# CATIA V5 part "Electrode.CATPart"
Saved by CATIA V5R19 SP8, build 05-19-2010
Part number: Electrode
Nomenclature: 66
Material "Chrome": density 7190 kg/m3, Young's modulus 7e+10 Pa, Poisson ratio 0.3, thermal expansion 6.2e-06 1/K
Bounding box of the stored display mesh (mm): x -21 to 21, y -15 to 15, z 4.388 to 19.89
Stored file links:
  C:\Users\rphgr\Desktop\0_Tapis_TC520B_vitesse\Electrode.CATPart
  D:\Documents\1_Travail\1 - ac-limoges.fr\ac-limoges.fr\Emmanuel Maynard - STI2D_Turgot\3 - Supports\Tapis de course TC520B\Tapis de course TC520B_Ca\0_Tapis_TC520B_Conception.CATProduct
  D:\Documents\1_Travail\1 - ac-limoges.fr\ac-limoges.fr\Emmanuel Maynard - STI2D_Turgot\3 - Supports\Tapis de course TC520B\Tapis de course TC520B_Ca\Support Electrode_Sup.CATPart
  D:\Programmes\DassaultSysteme\win_b64\startup\materials\French\Catalog.CATMaterial
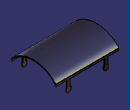
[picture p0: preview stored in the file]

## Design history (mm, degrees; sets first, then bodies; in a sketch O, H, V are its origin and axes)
AxisSystem1: origin (0, 0, 0), X (1, 0, 0), Y (0, 1, 0), Z (0, 0, 1)
Set1
  DatumSurface1
  DatumSurface2
Body1 (main body), material "Chrome"
  Sketch1 on YZ plane of AxisSystem1, origin (0, 0, 0), H (0, 1, 0), V (0, 0, 1)
    projected arc E1 centre (0, 0) radius 19.4 from (14.5, 12.8884) to (-14.5, 12.8884) ccw from face of DatumSurface1
    line L1 (14.5, 12.8884) -> (14.5, 2.8884)
    line L2 (-14.5, 12.8884) -> (-14.5, 2.8884)
    length L1 = 10
    length L2 = 10
    vertical: L1 V, L2 V
  Pad1: profile Sketch1, direction (-1, 0, 0), length 21, mirrored extent, thin wall 0, second thickness 0.5
  Sketch2 on face of Pad1, origin (0, 15, 0), H (-1, 0, 0), V (0, 0, 1)
    line L1 (-21, 11.8884) -> (-13.5, 11.8884)
    line L2 (-13.5, 11.8884) -> (-13.5, 7.3884)
    line L3 (-13.5, 7.3884) -> (-14, 7.3884)
    line L4 (-14, 7.3884) -> (-14, 5.8884)
    arc A1 centre (-12.5, 5.8884) radius 1.5 from (-14, 5.8884) to (-11, 5.8884) ccw
    point P6 (-12.5, 5.8884)
    line L5 (-11, 5.8884) -> (-11, 7.3884)
    point P8 (-11, 7.3884)
    line L6 (-11, 7.3884) -> (-11.5, 7.3884)
    line L7 (-11.5, 7.3884) -> (-11.5, 11.8884)
    point P10 (-11.5, 11.8884)
    line L8 (-11.5, 11.8884) -> (0, 11.8884)
    line L9 (0, 11.8884) -> (0, 2.8884)
    line L10 (0, 2.8884) -> (-21, 2.8884)
    line L11 (-21, 2.8884) -> (-21, 11.8884)
    reference intersected line E1 (-21, 8.8741) -> (-21, 13.0785) from start face of Pad1
    reference projected line E2 (41.8, 12.8884) -> (0, 12.8884) from edge of DatumSurface1
    reference projected line E3 (0, 2.8884) -> (41.8, 2.8884) from edge [face of Pad1 | face of Pad1]
    distance L4 L5 = 3
    distance L2 L4 = 0.5
    distance L7 L5 = 0.5
    distance P6 L8 = 6
    distance L3 L1 = 4.5
    distance L11 L2 = 7.5
    distance L1 E2 = 1
    horizontal: L1 H, L3 H, L6 H, L8 H, L10 H
    vertical: L2 V, L4 V, L9 V, L11 V
    tangency: A1 L4, L5 A1
    coincidence: P8 L3, P10 L1, L11 E1, L10 E3, L9 V
  Pocket1: profile Sketch2, direction (0, -1, 0), through (limit type 3)
  Mirror1: of Pocket1, about YZ plane of AxisSystem1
